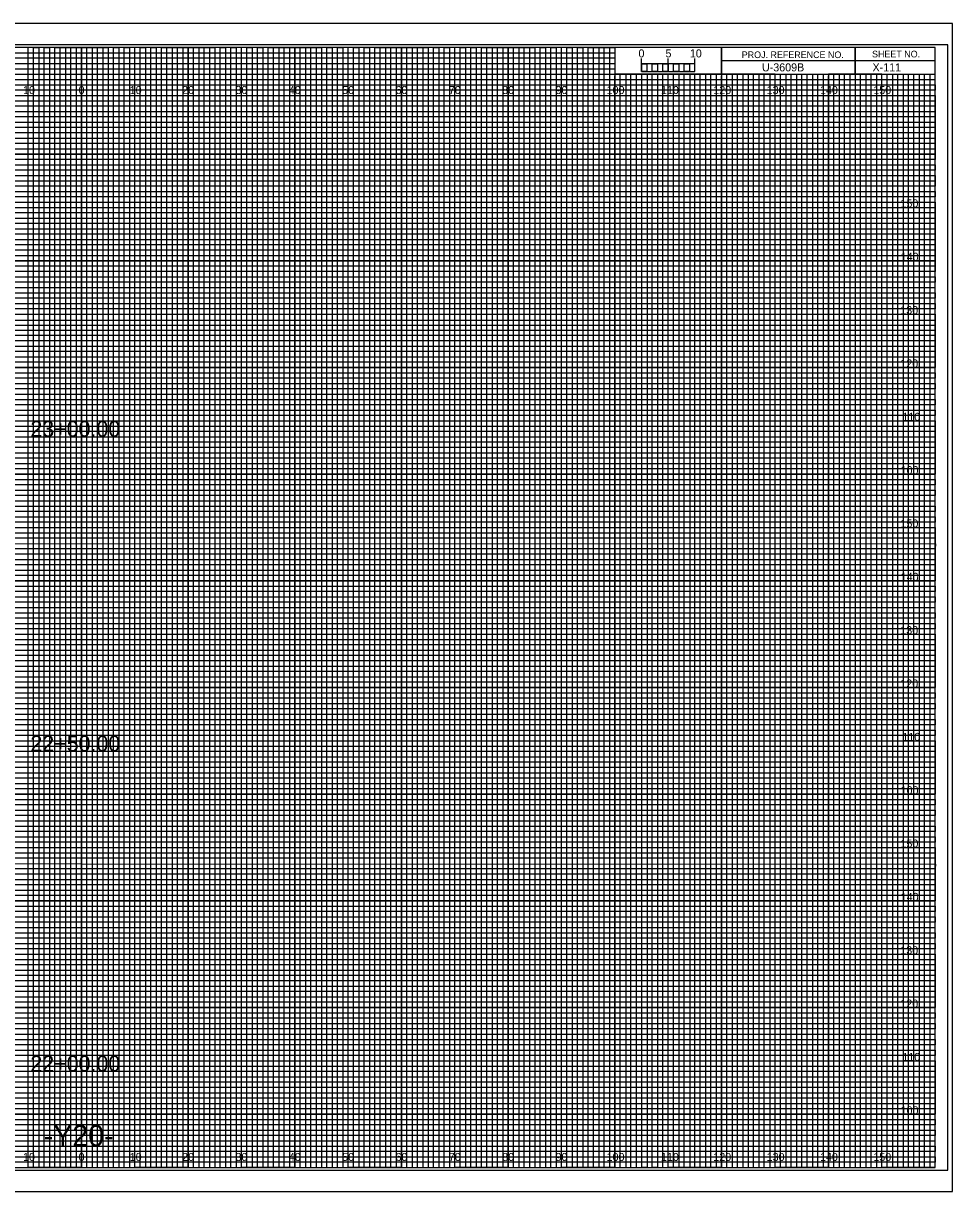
# Model space of a CAD drawing. Extents: x -13 to 323, y -5 to 2634.
# Drawn here: x 149.1 to 323.3, y 1755.5 to 1974.5 of the extents above; entities that cross this region are included whole.
import ezdxf

# ---------------------------------------------------------------- set-up
doc = ezdxf.new("R2010")
doc.units = 0
for name, color, linetype in [('Exist CMT Pavement', 7, 'Continuous'), ('Exist Cross Section Cell', 7, 'Continuous'), ('Exist XS Center Line Elevation Label', 7, 'Continuous'), ('Exist XS Ground Line', 7, 'Continuous'), ('Prop CMT Pvmt Course 1 Wedge', 7, 'Continuous'), ('Prop CMT Pvmt Course 2', 7, 'Continuous'), ('Prop CMT Pvmt Course 2 Wedge', 7, 'Continuous'), ('Prop CMT Pvmt Course 3', 7, 'Continuous'), ('Prop CMT Pvmt Course 3 Wedge', 7, 'Continuous'), ('Prop CMT Pvmt Surface', 7, 'Continuous'), ('Prop CMT Pvmt Wedge Surface 1', 7, 'Continuous'), ('Prop CMT Pvmt Wedge Surface 2', 7, 'Continuous'), ('Prop CMT Shld Paved Course 1', 7, 'Continuous'), ('Prop CMT Shld Paved Course 2', 7, 'Continuous'), ('Prop CMT Shld Paved Course 3', 7, 'Continuous'), ('Prop CMT Subgrade Earthwork', 7, 'Continuous'), ('Scratch_Level_0', 7, 'Continuous')]:
    doc.layers.add(name, color=color, linetype=linetype)

msp = doc.modelspace()

# ---------------------------------------------------------------- linework, layer by layer
at = {"layer": 'Exist XS Center Line Elevation Label'}
for points in [[(145, 1760), (155, 1760), (155, 1970), (165, 1970), (165, 1760), (175, 1760), (175, 1970), (185, 1970), (185, 1760), (195, 1760), (195, 1970), (205, 1970), (205, 1760), (215, 1760), (215, 1970), (225, 1970), (225, 1760), (235, 1760), (235, 1970), (245, 1970), (245, 1760), (255, 1760), (255, 1970), (259.93, 1970), (260, 1970), (260, 1965), (264.99, 1965), (264.99, 1760), (275, 1760), (275, 1965), (285, 1965), (285, 1760), (295, 1760), (295, 1965), (305, 1965), (305, 1760), (315, 1760), (315, 1965)], [(0, 1965), (275, 1965)], [(0, 1945), (320, 1945), (320, 1955), (0, 1955)], [(0, 1925), (320, 1925), (320, 1935), (0, 1935)], [(0, 1905), (320, 1905), (320, 1915), (0, 1915)], [(0, 1885), (320, 1885), (320, 1895), (0, 1895)], [(0, 1865), (320, 1865), (320, 1875), (0, 1875)], [(0, 1845), (320, 1845), (320, 1855), (0, 1855)], [(0, 1825), (320, 1825), (320, 1835), (0, 1835)], [(0, 1805), (320, 1805), (320, 1815), (0, 1815)], [(0, 1785), (320, 1785), (320, 1795), (0, 1795)], [(0, 1765), (320, 1765), (320, 1775), (0, 1775)]]:
    msp.add_lwpolyline(points, dxfattribs=at)
at = {"layer": 'Exist XS Ground Line'}
for p, q in [((150, 1970), (140, 1970)), ((150, 1760), (150, 1970)), ((170, 1970), (160, 1970)), ((160, 1970), (160, 1760)), ((170, 1760), (170, 1970)), ((190, 1970), (180, 1970)), ((180, 1970), (180, 1760)), ((190, 1760), (190, 1970)), ((210, 1970), (200, 1970)), ((200, 1970), (200, 1760)), ((210, 1760), (210, 1970)), ((230, 1970), (220, 1970)), ((220, 1970), (220, 1760)), ((230, 1760), (230, 1970)), ((250, 1970), (240, 1970)), ((240, 1970), (240, 1760)), ((250, 1760), (250, 1970)), ((260, 1970), (260, 1760)), ((270, 1760), (270, 1965)), ((290, 1965), (280, 1965)), ((280, 1965), (280, 1760)), ((290, 1760), (290, 1965)), ((310, 1965), (300, 1965)), ((300, 1965), (300, 1760)), ((310, 1760), (310, 1965)), ((160, 1760), (150, 1760)), ((180, 1760), (170, 1760)), ((200, 1760), (190, 1760)), ((220, 1760), (210, 1760)), ((240, 1760), (230, 1760)), ((260, 1760), (250, 1760)), ((280, 1760), (270, 1760)), ((300, 1760), (290, 1760)), ((320, 1760), (310, 1760)), ((320, 1760), (320, 1760))]:
    msp.add_line(p, q, dxfattribs=at)
for points in [[(0, 1960), (320, 1960), (320, 1950), (0, 1950)], [(0, 1940), (320, 1940), (320, 1930), (0, 1930)], [(0, 1920), (320, 1920), (320, 1910), (0, 1910)], [(0, 1900), (320, 1900), (320, 1890), (0, 1890)], [(0, 1880), (320, 1880), (320, 1870), (0, 1870)], [(0, 1860), (320, 1860), (320, 1850), (0, 1850)], [(0, 1840), (320, 1840), (320, 1830), (0, 1830)], [(0, 1820), (320, 1820), (320, 1810), (0, 1810)], [(0, 1800), (320, 1800), (320, 1790), (0, 1790)], [(0, 1780), (320, 1780), (320, 1770), (0, 1770)]]:
    msp.add_lwpolyline(points, dxfattribs=at)
at = {"layer": 'Prop CMT Pvmt Course 1 Wedge'}
for p, q in [((323.3, 1974.5), (-13.4, 1974.5)), ((-13.4, 1755.5), (323.3, 1755.5))]:
    msp.add_line(p, q, dxfattribs=at)
at = {"layer": 'Prop CMT Pvmt Course 2'}
msp.add_lwpolyline([(-13.4, 1755.5), (323.3, 1755.5), (323.3, 1974.5), (-13.4, 1974.5)], close=True, dxfattribs=at)
at = {"layer": 'Prop CMT Pvmt Course 3'}
msp.add_lwpolyline([(-10.8, 1759.5), (322.4, 1759.5), (322.4, 1970.5), (-10.8, 1970.5)], close=True, dxfattribs=at)
at = {"layer": 'Prop CMT Shld Paved Course 1'}
for p, q in [((305, 1970), (305, 1965)), ((305, 1965), (305, 1970)), ((280, 1967.5), (280, 1965)), ((320, 1967.49), (280, 1967.49)), ((280, 1965), (320, 1965))]:
    msp.add_line(p, q, dxfattribs=at)
for points in [[(320, 1970), (0, 1970), (0, 1760), (320, 1760)], [(280, 1970), (260, 1970), (260, 1965.03), (280, 1965.03)], [(320, 1970), (280, 1970), (280, 1965), (320, 1965)]]:
    msp.add_lwpolyline(points, close=True, dxfattribs=at)
at = {"layer": 'Prop CMT Shld Paved Course 2'}
for p, q in [((267, 1965), (266.01, 1965)), ((266.01, 1965), (266.01, 1760)), ((267, 1760), (267, 1965)), ((269, 1965), (268, 1965)), ((268, 1965), (268, 1760)), ((269, 1760), (269, 1965)), ((266.01, 1760), (265, 1760)), ((268, 1760), (267, 1760))]:
    msp.add_line(p, q, dxfattribs=at)
for points in [[(150, 1760), (151, 1760), (151, 1970), (152, 1970), (152, 1760)], [(152, 1760), (153, 1760), (153, 1970), (154, 1970), (154, 1760)], [(155, 1760), (156, 1760), (156, 1970), (157, 1970), (157, 1760)], [(157, 1760), (158, 1760), (158, 1970), (159, 1970), (159, 1760)], [(160, 1760), (161, 1760), (161, 1970), (162, 1970), (162, 1760)], [(162, 1760), (163, 1760), (163, 1970), (164, 1970), (164, 1760)], [(165, 1760), (166, 1760), (166, 1970), (167, 1970), (167, 1760)], [(167, 1760), (168, 1760), (168, 1970), (169, 1970), (169, 1760)], [(170, 1760), (171, 1760), (171, 1970), (172, 1970), (172, 1760)], [(172, 1760), (173, 1760), (173, 1970), (174, 1970), (174, 1760)], [(175, 1760), (176, 1760), (176, 1970), (177, 1970), (177, 1760)], [(177, 1760), (178, 1760), (178, 1970), (179, 1970), (179, 1760)], [(180, 1760), (181, 1760), (181, 1970), (182, 1970), (182, 1760)], [(182, 1760), (183, 1760), (183, 1970), (184, 1970), (184, 1760)], [(185, 1760), (186, 1760), (186, 1970), (187, 1970), (187, 1760)], [(187, 1760), (188, 1760), (188, 1970), (189, 1970), (189, 1760)], [(190, 1760), (191, 1760), (191, 1970), (192, 1970), (192, 1760)], [(192, 1760), (193, 1760), (193, 1970), (194, 1970), (194, 1760)], [(195, 1760), (196, 1760), (196, 1970), (197, 1970), (197, 1760)], [(197, 1760), (198, 1760), (198, 1970), (199, 1970), (199, 1760)], [(200, 1760), (201, 1760), (201, 1970), (202, 1970), (202, 1760)], [(202, 1760), (203, 1760), (203, 1970), (204, 1970), (204, 1760)], [(205, 1760), (206, 1760), (206, 1970), (207, 1970), (207, 1760)], [(207, 1760), (208, 1760), (208, 1970), (209, 1970), (209, 1760)], [(210, 1760), (211, 1760), (211, 1970), (212, 1970), (212, 1760)], [(212, 1760), (213, 1760), (213, 1970), (214, 1970), (214, 1760)], [(215, 1760), (216, 1760), (216, 1970), (217, 1970), (217, 1760)], [(217, 1760), (218, 1760), (218, 1970), (219, 1970), (219, 1760)], [(220, 1760), (221, 1760), (221, 1970), (222, 1970), (222, 1760)], [(222, 1760), (223, 1760), (223, 1970), (224, 1970), (224, 1760)], [(225, 1760), (226, 1760), (226, 1970), (227, 1970), (227, 1760)], [(227, 1760), (228, 1760), (228, 1970), (229, 1970), (229, 1760)], [(230, 1760), (231, 1760), (231, 1970), (232, 1970), (232, 1760)], [(232, 1760), (233, 1760), (233, 1970), (234, 1970), (234, 1760)], [(235, 1760), (236, 1760), (236, 1970), (237, 1970), (237, 1760)], [(237, 1760), (238, 1760), (238, 1970), (239, 1970), (239, 1760)], [(240, 1760), (241, 1760), (241, 1970), (242, 1970), (242, 1760)], [(242, 1760), (243, 1760), (243, 1970), (244, 1970), (244, 1760)], [(245, 1760), (246, 1760), (246, 1970), (247, 1970), (247, 1760)], [(247, 1760), (248, 1760), (248, 1970), (249, 1970), (249, 1760)], [(250, 1760), (251, 1760), (251, 1970), (252, 1970), (252, 1760)], [(252, 1760), (253, 1760), (253, 1970), (254, 1970), (254, 1760)], [(255, 1760), (256, 1760), (256, 1970), (257, 1970), (257, 1760)], [(257, 1760), (258, 1760), (258, 1970), (259, 1970), (259, 1760)], [(260, 1760), (261, 1760), (261, 1965), (262.02, 1965), (262.02, 1760)], [(262, 1760), (263, 1760), (263, 1965), (263.99, 1965), (263.99, 1760)], [(270, 1760), (270.98, 1760), (270.98, 1965), (272, 1965), (272, 1760)], [(272, 1760), (273, 1760), (273, 1965), (274.05, 1965), (274.05, 1760)], [(275, 1760), (276, 1760), (276, 1965), (277, 1965), (277, 1760)], [(277, 1760), (278, 1760), (278, 1965), (279, 1965), (279, 1760)], [(280, 1760), (281, 1760), (281, 1965), (282, 1965), (282, 1760)], [(282, 1760), (283, 1760), (283, 1965), (284, 1965), (284, 1760)], [(285, 1760), (286, 1760), (286, 1965), (287, 1965), (287, 1760)], [(287, 1760), (288, 1760), (288, 1965), (289, 1965), (289, 1760)], [(290, 1760), (291, 1760), (291, 1965), (292, 1965), (292, 1760)], [(292, 1760), (293, 1760), (293, 1965), (294, 1965), (294, 1760)], [(295, 1760), (296, 1760), (296, 1965), (297, 1965), (297, 1760)], [(297, 1760), (298, 1760), (298, 1965), (299, 1965), (299, 1760)], [(300, 1760), (301, 1760), (301, 1965), (302, 1965), (302, 1760)], [(302, 1760), (303, 1760), (303, 1965), (304, 1965), (304, 1760)], [(305, 1760), (306, 1760), (306, 1965), (307, 1965), (307, 1760)], [(307, 1760), (308, 1760), (308, 1965), (309, 1965), (309, 1760)], [(310, 1760), (311, 1760), (311, 1965), (312, 1965), (312, 1760)], [(312, 1760), (313, 1760), (313, 1965), (314, 1965), (314, 1760)], [(315, 1760), (316, 1760), (316, 1965), (317, 1965), (317, 1760)], [(317, 1760), (318, 1760), (318, 1965), (319, 1965), (319, 1760)]]:
    msp.add_lwpolyline(points, dxfattribs=at)
at = {"layer": 'Prop CMT Shld Paved Course 3'}
for p, q in [((265, 1965.49), (265, 1967.9)), ((265, 1966.9), (265, 1967.9)), ((270, 1965.49), (270, 1967.9)), ((275, 1965.49), (275, 1967.9)), ((275, 1966.9), (275, 1967.9))]:
    msp.add_line(p, q, dxfattribs=at)
for points in [[(275, 1966.9), (265, 1966.9), (265, 1965.49), (275, 1965.49)], [(265, 1966.9), (266, 1966.9), (266, 1965.49), (265, 1965.49)], [(267, 1966.9), (268, 1966.9), (268, 1965.49), (267, 1965.49)], [(269, 1966.9), (270, 1966.9), (270, 1965.49), (269, 1965.49)], [(271, 1966.9), (272, 1966.9), (272, 1965.49), (271, 1965.49)], [(273, 1966.9), (274, 1966.9), (274, 1965.49), (273, 1965.49)]]:
    msp.add_lwpolyline(points, close=True, dxfattribs=at)
at = {"layer": 'Prop CMT Subgrade Earthwork'}
for p, q in [((150, 1760), (150, 1970)), ((160, 1760), (160, 1970)), ((170, 1760), (170, 1970)), ((180, 1760), (180, 1970)), ((190, 1760), (190, 1970)), ((200, 1760), (200, 1970)), ((210, 1760), (210, 1970)), ((220, 1760), (220, 1970)), ((230, 1760), (230, 1970)), ((240, 1760), (240, 1970)), ((250, 1760), (250, 1970)), ((260, 1760), (260, 1964.69)), ((270, 1760), (270, 1964.69)), ((280, 1760), (280, 1964.69)), ((290, 1760), (290, 1964.69)), ((300, 1760), (300, 1964.69)), ((310, 1760), (310, 1964.69)), ((0, 1960), (320, 1960)), ((0, 1950), (320, 1950)), ((0, 1940), (320, 1940)), ((0, 1930), (320, 1930)), ((0, 1920), (320, 1920)), ((0, 1910), (320, 1910)), ((0, 1900), (320, 1900)), ((0, 1890), (320, 1890)), ((0, 1880), (320, 1880)), ((0, 1870), (320, 1870)), ((0, 1860), (320, 1860)), ((0, 1850), (320, 1850)), ((0, 1840), (320, 1840)), ((0, 1830), (320, 1830)), ((0, 1820), (320, 1820)), ((0, 1810), (320, 1810)), ((0, 1800), (320, 1800)), ((0, 1790), (320, 1790)), ((0, 1780), (320, 1780)), ((0, 1770), (320, 1770))]:
    msp.add_line(p, q, dxfattribs=at)
at = {"layer": 'Scratch_Level_0'}
for p, q in [((0, 1969), (260, 1969)), ((260, 1969), (260, 1967.98)), ((260, 1967.98), (0, 1967.98)), ((0, 1967), (260, 1967)), ((260, 1967), (260, 1965.89)), ((260, 1965.89), (0, 1965.89)), ((0, 1964), (320, 1964))]:
    msp.add_line(p, q, dxfattribs=at)
for points in [[(0, 1963), (270, 1963), (320, 1963), (320, 1962), (0, 1962)], [(0, 1961), (320, 1961), (320, 1959), (0, 1959)], [(0, 1958), (320, 1958), (320, 1957), (0, 1956.98)], [(0, 1956), (320, 1956), (320, 1954), (0, 1954)], [(0, 1953), (320, 1953), (320, 1952), (0, 1952)], [(0, 1951), (320, 1951), (320, 1949), (0, 1949)], [(0, 1948), (320, 1948), (320, 1947), (0, 1947)], [(0, 1946), (320, 1946), (320, 1944), (0, 1944)], [(0, 1943), (320, 1943), (320, 1942), (0, 1942)], [(0, 1941), (320, 1941), (320, 1939), (0, 1939)], [(0, 1938), (320, 1938), (320, 1937), (0, 1937)], [(0, 1936), (320, 1936), (320, 1933.95), (320, 1933), (320, 1932), (0, 1932)], [(0, 1934), (320, 1934), (320, 1933), (0, 1933)], [(0, 1931), (320, 1931), (320, 1929), (0, 1929.03)], [(0, 1929.03), (320, 1929), (320, 1928), (0, 1928)], [(0, 1927), (320, 1927), (320, 1926), (0, 1926)], [(0, 1924), (320, 1924), (320, 1923), (0, 1923)], [(0, 1922), (320, 1922), (320, 1921), (0, 1921)], [(-0.07, 1918.89), (320, 1918.89), (320, 1917.88), (-0.07, 1917.88)], [(0, 1917), (320, 1917), (320, 1916), (0, 1916)], [(0, 1914), (320, 1914), (320, 1913), (0, 1913)], [(0, 1912), (320, 1912), (320, 1911), (0, 1911)], [(0, 1909), (320, 1909), (320, 1908), (0, 1908)], [(0, 1907), (320, 1907), (320, 1906), (0, 1906)], [(0, 1904), (320, 1904), (320, 1903), (0, 1903)], [(0, 1902), (320, 1902), (320, 1901), (0, 1901)], [(0, 1899), (320, 1899), (319.99, 1897.98), (0, 1898)], [(0, 1897), (320, 1897), (320, 1896), (0, 1896)], [(0, 1894), (320, 1894), (320, 1893), (0, 1893)], [(0, 1892), (320, 1892), (320, 1891), (0, 1891)], [(0, 1889), (320, 1889), (320, 1888), (0, 1888)], [(0, 1887), (320, 1887), (320, 1886), (0, 1886)], [(0, 1884), (320, 1884), (320, 1883), (0, 1883)], [(0, 1882), (320, 1882), (320, 1881), (0, 1881)], [(0, 1879), (320, 1879), (320, 1878), (0, 1878)], [(0, 1876.99), (320.07, 1876.91), (320, 1876), (0, 1876)], [(0, 1874), (320, 1874), (320, 1873), (0, 1873)], [(0, 1872), (320, 1872), (320, 1871), (0, 1871)], [(0, 1869), (320, 1869), (320, 1868), (0, 1868)], [(0, 1867), (320, 1867), (320, 1866), (0, 1866)], [(0, 1864), (320, 1864), (320, 1863), (0, 1863)], [(0, 1862), (320, 1862), (320, 1861), (0, 1861)], [(0, 1859), (320, 1859), (320, 1858), (0, 1858)], [(0, 1857), (320, 1857), (320, 1856), (0, 1856)], [(0, 1854), (320, 1854), (320, 1853), (0, 1853)], [(0, 1852), (320, 1852), (320, 1851), (0, 1851)], [(0, 1849), (320, 1849), (320, 1848), (0, 1848)], [(0, 1847), (320, 1847), (320, 1846), (0, 1846)], [(0, 1844), (320, 1844), (320, 1843), (0, 1843)], [(0, 1842), (320, 1842), (320, 1841), (0, 1841)], [(0, 1839), (320, 1839), (319.99, 1837.98), (0, 1838)], [(0, 1837), (320, 1837), (320, 1836), (0, 1836)], [(0, 1834), (320, 1834), (320, 1833), (0, 1833)], [(0, 1832), (320, 1832), (320, 1831), (0, 1831)], [(0, 1829), (320, 1829), (320, 1828), (0, 1828)], [(0, 1827), (320, 1827), (320, 1826), (0, 1826)], [(0, 1824), (320, 1824), (320, 1823), (0, 1823)], [(0, 1822), (320, 1822), (320, 1821), (0, 1821)], [(0, 1819), (320, 1819), (320, 1818), (0, 1818)], [(0, 1816.99), (320.07, 1816.91), (320, 1816), (0, 1816)], [(0, 1814), (320, 1814), (320, 1813), (0, 1813)], [(0, 1812), (320, 1812), (320, 1811), (0, 1811)], [(0, 1809), (320, 1809), (320, 1808), (0, 1808)], [(0, 1807), (320, 1807), (320, 1806), (0, 1806)], [(0, 1804), (320, 1804), (320, 1803), (0, 1803)], [(0, 1802), (320, 1802), (320, 1801), (0, 1801)], [(0, 1799), (320, 1799), (320, 1798), (0, 1798)], [(0, 1797), (320, 1797), (320, 1796), (0, 1796)], [(0, 1794), (320, 1794), (320, 1793), (0, 1793)], [(0, 1792), (320, 1792), (320, 1791), (0, 1791)], [(0, 1789), (320, 1789), (320, 1788), (0, 1788)], [(0, 1787), (320, 1787), (320, 1786), (0, 1786)], [(0, 1784), (320, 1784), (320, 1783), (0, 1783)], [(0, 1782), (320, 1782), (320, 1781), (0, 1781)], [(0, 1779), (320, 1779), (320, 1778), (0, 1778)], [(0, 1777), (320, 1777), (320, 1776), (0, 1776)], [(0, 1774), (320, 1774), (320, 1773), (0, 1773)], [(0, 1772), (320, 1772), (320, 1771), (0, 1771)], [(0, 1769), (320, 1769), (320, 1768), (0, 1768)], [(0, 1767), (320, 1767), (320, 1766), (0, 1766)], [(0, 1764), (320, 1764), (320, 1763), (0, 1763)], [(0, 1762), (320, 1762), (320, 1761), (0, 1761)]]:
    msp.add_lwpolyline(points, dxfattribs=at)

# ---------------------------------------------------------------- texts
at = {"layer": 'Exist CMT Pavement'}
msp.add_text('X-111', height=1.5, dxfattribs=at).set_placement((308.28, 1965.5))
at = {"layer": 'Exist Cross Section Cell'}
for s, p in [('10', (149.04, 1961.25)), ('0', (159.45, 1961.25)), ('0', (159.45, 1961.25)), ('10', (169.04, 1961.25)), ('20', (178.86, 1961.25)), ('30', (188.86, 1961.25)), ('40', (198.86, 1961.25)), ('50', (208.86, 1961.25)), ('60', (218.86, 1961.25)), ('70', (228.86, 1961.25)), ('80', (238.86, 1961.25)), ('90', (248.86, 1961.25)), ('100', (258.44, 1961.25)), ('110', (268.62, 1961.25)), ('120', (278.44, 1961.25)), ('130', (288.44, 1961.25)), ('140', (298.44, 1961.25)), ('150', (308.44, 1961.25)), ('10', (149.04, 1761.25)), ('0', (159.45, 1761.25)), ('0', (159.45, 1761.25)), ('10', (169.04, 1761.25)), ('20', (178.86, 1761.25)), ('30', (188.86, 1761.25)), ('40', (198.86, 1761.25)), ('50', (208.86, 1761.25)), ('60', (218.86, 1761.25)), ('70', (228.86, 1761.25)), ('80', (238.86, 1761.25)), ('90', (248.86, 1761.25)), ('100', (258.44, 1761.25)), ('110', (268.62, 1761.25)), ('120', (278.44, 1761.25)), ('130', (288.44, 1761.25)), ('140', (298.44, 1761.25)), ('150', (308.44, 1761.25))]:
    msp.add_text(s, height=1.5, dxfattribs=at).set_placement(p)
at = {"layer": 'Prop CMT Pvmt Course 2 Wedge'}
for s, p in [('150', (313.52, 1940)), ('140', (313.57, 1930)), ('130', (313.49, 1920)), ('120', (313.5, 1910)), ('110', (313.88, 1900)), ('100', (313.55, 1890)), ('150', (313.52, 1880)), ('140', (313.57, 1870)), ('130', (313.49, 1860)), ('120', (313.5, 1850)), ('110', (313.88, 1840)), ('100', (313.55, 1830)), ('150', (313.52, 1820)), ('140', (313.57, 1810)), ('130', (313.49, 1800)), ('120', (313.5, 1790)), ('110', (313.88, 1780)), ('100', (313.55, 1770))]:
    msp.add_text(s, height=1.5, dxfattribs=at).set_placement(p)
at = {"layer": 'Prop CMT Pvmt Course 3 Wedge'}
for s, p in [('23+00.00', (150.41, 1897)), ('22+50.00', (150.41, 1838)), ('22+00.00', (150.41, 1778))]:
    msp.add_text(s, height=3, dxfattribs=at).set_placement(p)
at = {"layer": 'Prop CMT Pvmt Surface'}
msp.add_text('U-3609B', height=1.5, dxfattribs=at).set_placement((287.56, 1965.5))
at = {"layer": 'Prop CMT Pvmt Wedge Surface 1'}
msp.add_text('-Y20-', height=4, dxfattribs=at).set_placement((152.93, 1764))
at = {"layer": 'Prop CMT Pvmt Wedge Surface 2'}
for s, p in [('5', (269.47, 1968.12)), ('10', (274.04, 1968.12))]:
    msp.add_text(s, height=1.5, dxfattribs=at).set_placement(p)
at = {"layer": 'Prop CMT Shld Paved Course 1'}
for s, p in [('PROJ. REFERENCE NO.', (283.77, 1967.99)), ('SHEET NO.', (308.19, 1968.12))]:
    msp.add_text(s, height=1.25, dxfattribs=at).set_placement(p)
at = {"layer": 'Prop CMT Shld Paved Course 3'}
msp.add_text('0', height=1.5, dxfattribs=at).set_placement((264.41, 1968.12))

doc.saveas('drawing.dxf')
